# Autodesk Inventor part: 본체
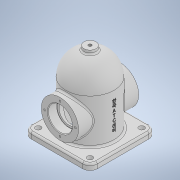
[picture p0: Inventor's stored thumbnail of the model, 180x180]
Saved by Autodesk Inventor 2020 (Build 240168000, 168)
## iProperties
Created: 2021-07
Part Number: 본체
Material: 일반
Document SubType Name: Modeling
Designer: Owner
Density: 1 g/cm^3
Appearance: 기본값
Author: Owner
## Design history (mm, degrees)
sketch "스케치1"
  geometry: C1 r 40 at (0, 0); 1 further point
  constraints: 1 centre point, 1 coincident
  dimensions: "d0" = 80 diameter of C1
extrude "돌출1" new body sketch "스케치1" distance "d1" = 124; taper "d2" = 0 deg
sketch "스케치2"
  geometry: 1 further point
fillet "모깎기1" dims "d3" = 40
feature "쉘1" dims "d4" = 8
sketch "스케치3"
  geometry: L1 (-55, 55)-(55, 55); L2 (55, 55)-(55, -55); L3 (55, -55)-(-55, -55); L4 (-55, -55)-(-55, 55); L5 (-55, 55)-(55, -55); L6 (55, 55)-(-55, -55); C1 r 32 at (0, 0) reference; 1 further point
  constraints: 12 end point, 2 midpoint, 2 parallel, 1 horizontal, 1 perpendicular
  dimensions: "d5" = 110 distance of L2.end L3.end; "d6" = 110 distance of L1.end L2.end
extrude "돌출2" join sketch "스케치3" distance "d7" = 10; taper "d8" = 0 deg
fillet "모깎기2" dims "d9" = 12
fillet "모깎기3" dims "d10" = 3
sketch "스케치4"
  geometry: A1 r 9 centre (-43, 43) between (-43, 52) and (-52, 43) reference; A2 r 9 centre (43, 43) between (52, 43) and (43, 52) reference; A3 r 12 centre (43, -43) between (43, -55) and (55, -43) reference; A4 r 12 centre (-43, -43) between (-55, -43) and (-43, -55) reference; 5 further points
  constraints: 4 coincident
hole "구멍1" sketch "스케치4" at (-43, -43), (43, -43), (43, 43), (-43, 43) diameter "d11" = 9; stored, may be unused: countersink angle "d15" = 90 deg, drill point angle "d17" = 0 deg; dims "d12" = 6, "d13" = 4, "d14" = 2, "d16" = 8
node "작업 평면1"
sketch "스케치5"
  geometry: L1 (-43, 0)-(43, 0) reference; C1 r 31 at (0, 48); 2 further points
  constraints: 1 centre point, 1 midpoint, 1 vertical alignment
  dimensions: "d19" = 62 diameter of C1; "d20" = 48 distance from line of L1 C1.centre
extrude "돌출3" join sketch "스케치5" stored distance "d21" = 10; taper "d22" = 0 deg
sketch "스케치6"
  geometry: C1 r 31 at (0, 0) reference; 2 further points
  constraints: 1 coincident
hole "구멍2" sketch "스케치6" at (0, 0) diameter "d23" = 33; stored, may be unused: countersink angle "d27" = 90 deg, drill point angle "d29" = 0 deg; dims "d24" = 6, "d25" = 40, "d26" = 15, "d28" = 8
sketch "스케치7"
  geometry: C1 r 31 at (0, 0) reference; A1 r 25.5 centre (0, 0) between (0, 25.5) and (-25.5, 0); 3 further points
  constraints: 4 point on circle, 2 horizontal alignment, 2 vertical alignment, 1 centre point, 1 coincident
  dimensions: "d30" = 51 diameter of A1
hole "구멍3" sketch "스케치7" at (0, 25.5), (-25.5, 0), (25.5, 0), (0, -25.5) diameter "d31" = 3.242; stored, may be unused: countersink angle "d35" = 90 deg, drill point angle "d37" = 118 deg; dims "d32" = 8, "d33" = 40, "d34" = 15, "d36" = 10
fillet "모깎기4" dims "d38" = 3
node "작업 평면2"
sketch "스케치8"
  geometry: C1 r 10 at (0, 0); 1 further point
  constraints: 1 centre point, 1 coincident
  dimensions: "d40" = 20 diameter of C1
extrude "돌출4" join sketch "스케치8" stored distance "d41" = 10; taper "d42" = 0 deg
sketch "스케치9"
  geometry: C1 r 10 at (0, 0) reference; 2 further points
  constraints: 1 coincident
hole "구멍4" sketch "스케치9" at (0, 0) diameter "d43" = 5.1881; stored, may be unused: countersink angle "d47" = 90 deg, drill point angle "d49" = 0 deg; dims "d44" = 12, "d45" = 40, "d46" = 15, "d48" = 16
fillet "모깎기5" dims "d50" = 3
node "작업 평면3"
sketch "스케치10"
  geometry: L1 (0, 43)-(0, -43) reference; 3 further points
  constraints: 1 horizontal alignment, 1 midpoint, 1 other
  dimensions: "d51" = 48 distance from line of L1 point (48, 0)
feature "엠보싱1" sketch "스케치10" dims "d1" = 124, "d2" = 0, "d9" = 12, "d52" = 0.5, "d53" = 0
chamfer "모따기1" distance "d54" = 1; stored, may be unused: second distance "d55" = 2, angle "d56" = 45 deg
chamfer "모따기2" distance "d57" = 1; stored, may be unused: second distance "d58" = 2, angle "d59" = 45 deg
fillet "모깎기6" dims "d60" = 0.3
node "솔리드1"
mirror "미러1"
mirror "미러2"
feature "A9D066F2-1C7D-4E18-AEED-F7BC21143FA4" dims "d23" = 33, "d24" = 6, "d25" = 40, "d26" = 15, "d27" = 90 deg, "d28" = 8, "d29" = 0
other parameters: "d39" = 129
